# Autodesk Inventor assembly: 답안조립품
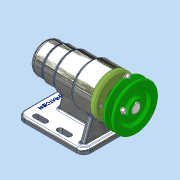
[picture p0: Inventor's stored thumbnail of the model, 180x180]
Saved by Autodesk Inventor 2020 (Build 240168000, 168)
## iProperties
Created: 2021-10
Part Number: 답안조립품
Document SubType Name: Assembly
Designer: user
Author: user
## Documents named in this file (12)
- C:\Users\user\Desktop\711007V1016\답안조립품.iam
- C:\Users\user\Desktop\711007V1016\V벨트풀리.ipt
- C:\Users\user\Desktop\711007V1016\멈춤나사 M3.ipt
- C:\Users\user\Desktop\711007V1016\베어링 6004.ipt
- C:\Users\user\Desktop\711007V1016\베어링 51202.ipt
- C:\Users\user\Desktop\711007V1016\본체.ipt
- C:\Users\user\Desktop\711007V1016\볼트 M4.ipt
- C:\Users\user\Desktop\711007V1016\어댑터슬리브.ipt
- C:\Users\user\Desktop\711007V1016\오일 실 20x35x7.ipt
- C:\Users\user\Desktop\711007V1016\축.ipt
- C:\Users\user\Desktop\711007V1016\커버.ipt
- C:\Users\user\Desktop\711007V1016\키 5x5.ipt
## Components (1 placed, 1 different names)
1. V벨트풀리:1
